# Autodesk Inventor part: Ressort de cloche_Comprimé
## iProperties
Shininess: 64.0
Length Units: 11269
Angle Units: 11279
Time Units: 11290
Mass Units: 11283
Length Display Precision: 3
Angle Display Precision: 2
Compacted: True
Part Number: Ressort de cloche_Comprimé
Document SubType Name: Modeling
Created: 2006-01
Material: Par défaut
Designer: riri
Density: 0.0
Volumn: 0.0
Area: 0.0
PropertySet Name: Model Information
Control State: 0
Master: False
Checked Out: False
Author: riri
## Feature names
1. Base1
